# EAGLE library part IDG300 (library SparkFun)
IDG300 This is a dual axis MEMs based gyroscope sensor from Invensense. The only gyro in currently available with two axis on one chip. Works very well. Schematic and footprint are not yet production proven. Spark Fun Electronics SKU : IC-IDG300
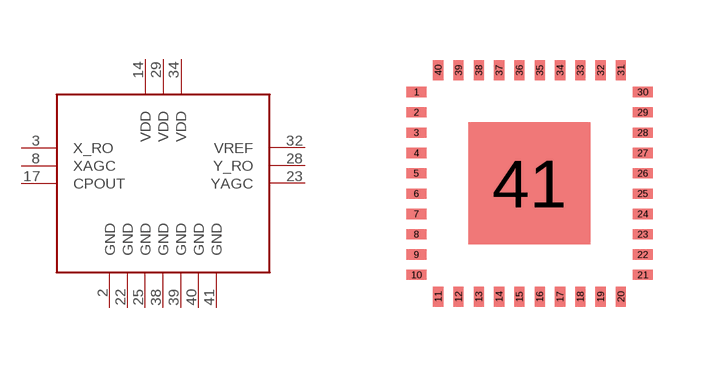
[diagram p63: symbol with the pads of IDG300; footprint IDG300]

Designator prefix -

## IDG300  [IDG300]
2  GND
3  X_RO
8  XAGC
14  VDD
17  CPOUT
22  GND
23  YAGC
25  GND
28  Y_RO
29  VDD
32  VREF
34  VDD
38  GND
39  GND
40  GND
41  GND

## Footprint IDG300 (pad centres in mm)
smd 0.508 x 0.254: 1 0,0; 2 0,-0.508; 3 0,-1.016; 4 0,-1.524; 5 0,-2.032; 6 0,-2.54; 7 0,-3.048; 8 0,-3.556; 9 0,-4.064; 10 0,-4.572; 21 5.664,-4.572; 22 5.664,-4.064; 23 5.664,-3.556; 24 5.664,-3.048; 25 5.664,-2.54; 26 5.664,-2.032; 27 5.664,-1.524; 28 5.664,-1.016; 29 5.664,-0.508; 30 5.664,0
smd 0.254 x 0.508: 11 0.546,-5.118; 12 1.054,-5.118; 13 1.562,-5.118; 14 2.07,-5.118; 15 2.578,-5.118; 16 3.086,-5.118; 17 3.594,-5.118; 18 4.102,-5.118; 19 4.61,-5.118; 20 5.118,-5.118; 31 5.118,0.546; 32 4.61,0.546; 33 4.102,0.546; 34 3.594,0.546; 35 3.086,0.546; 36 2.578,0.546; 37 2.07,0.546; 38 1.562,0.546; 39 1.054,0.546; 40 0.546,0.546
smd 3.048 x 3.048: 41 2.832,-2.286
